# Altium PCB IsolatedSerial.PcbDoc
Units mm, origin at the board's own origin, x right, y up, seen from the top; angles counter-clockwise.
Board outline 30.48 x 40.64 mm, 2 copper layers (Top Layer, Bottom Layer), stack 1.575 mm thick; 25 components, 18 nets, 112 pads, 19 vias.
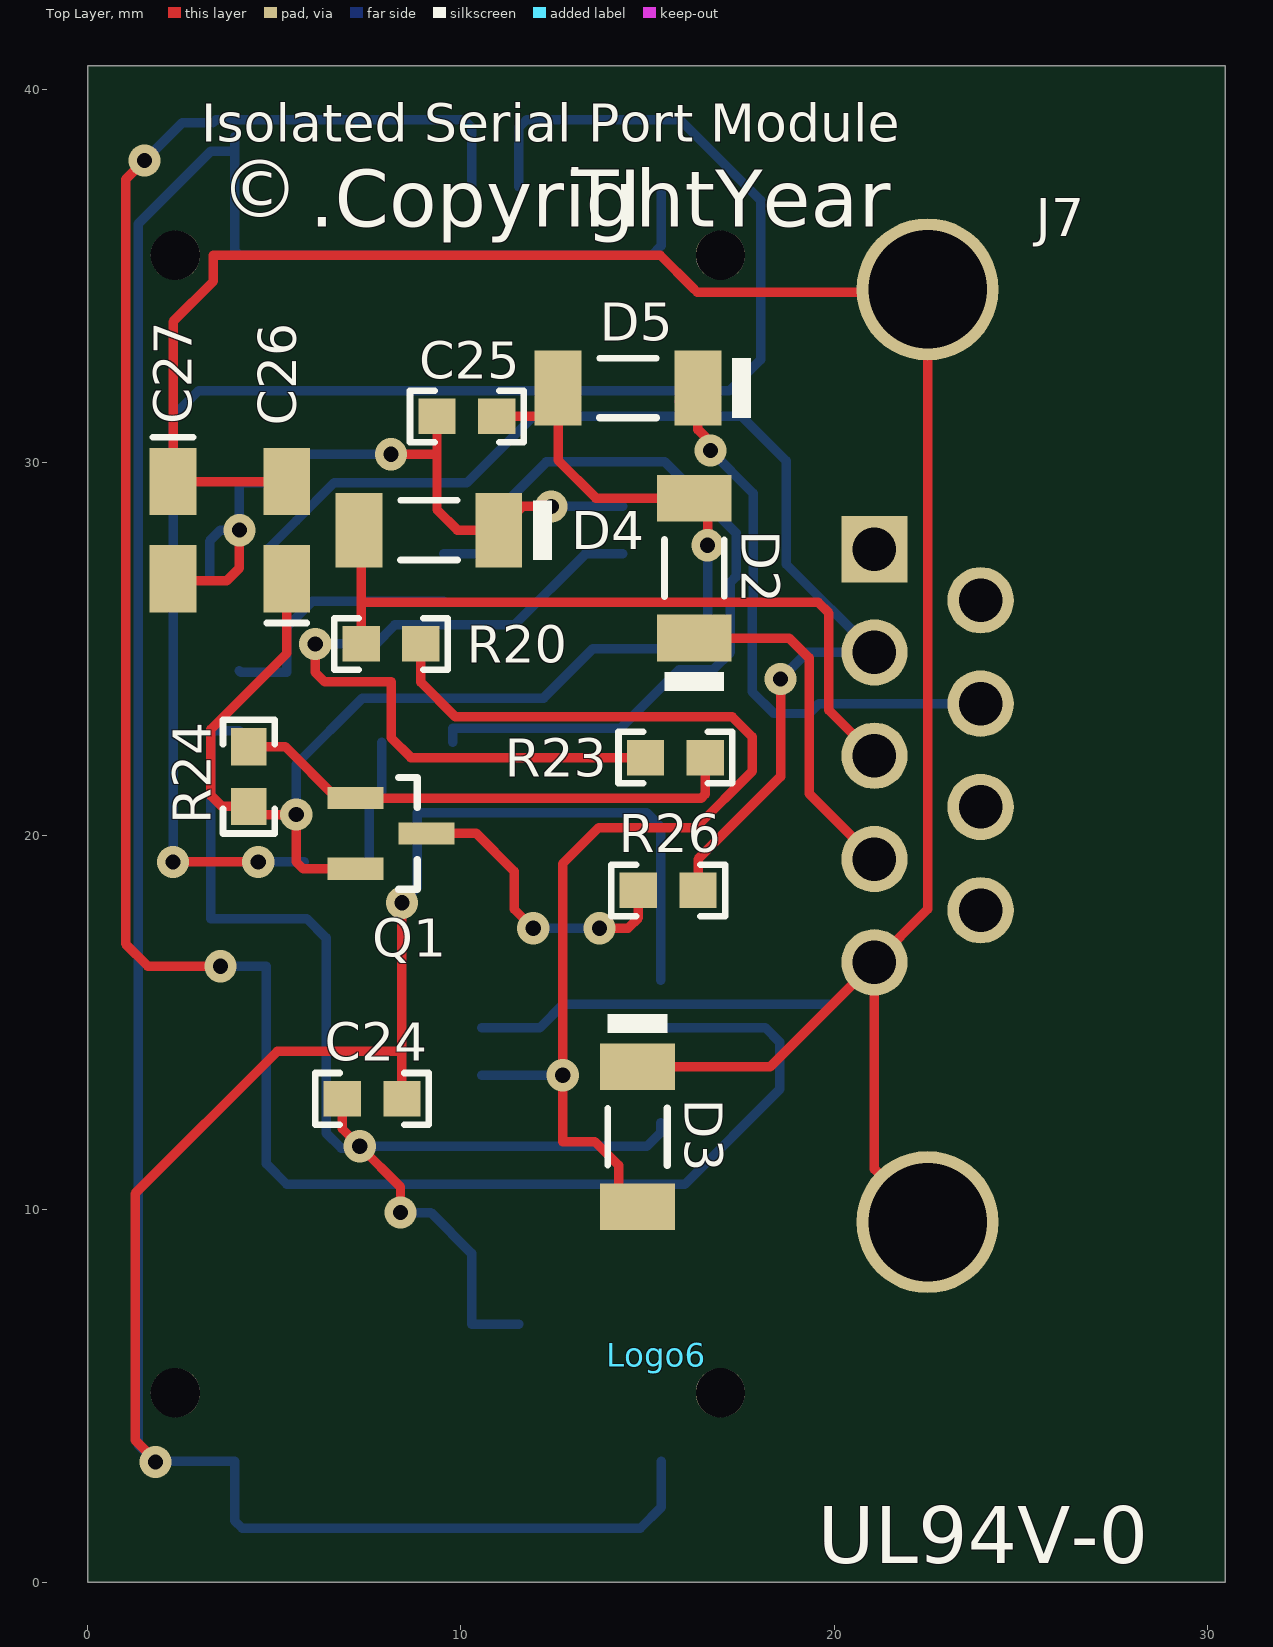
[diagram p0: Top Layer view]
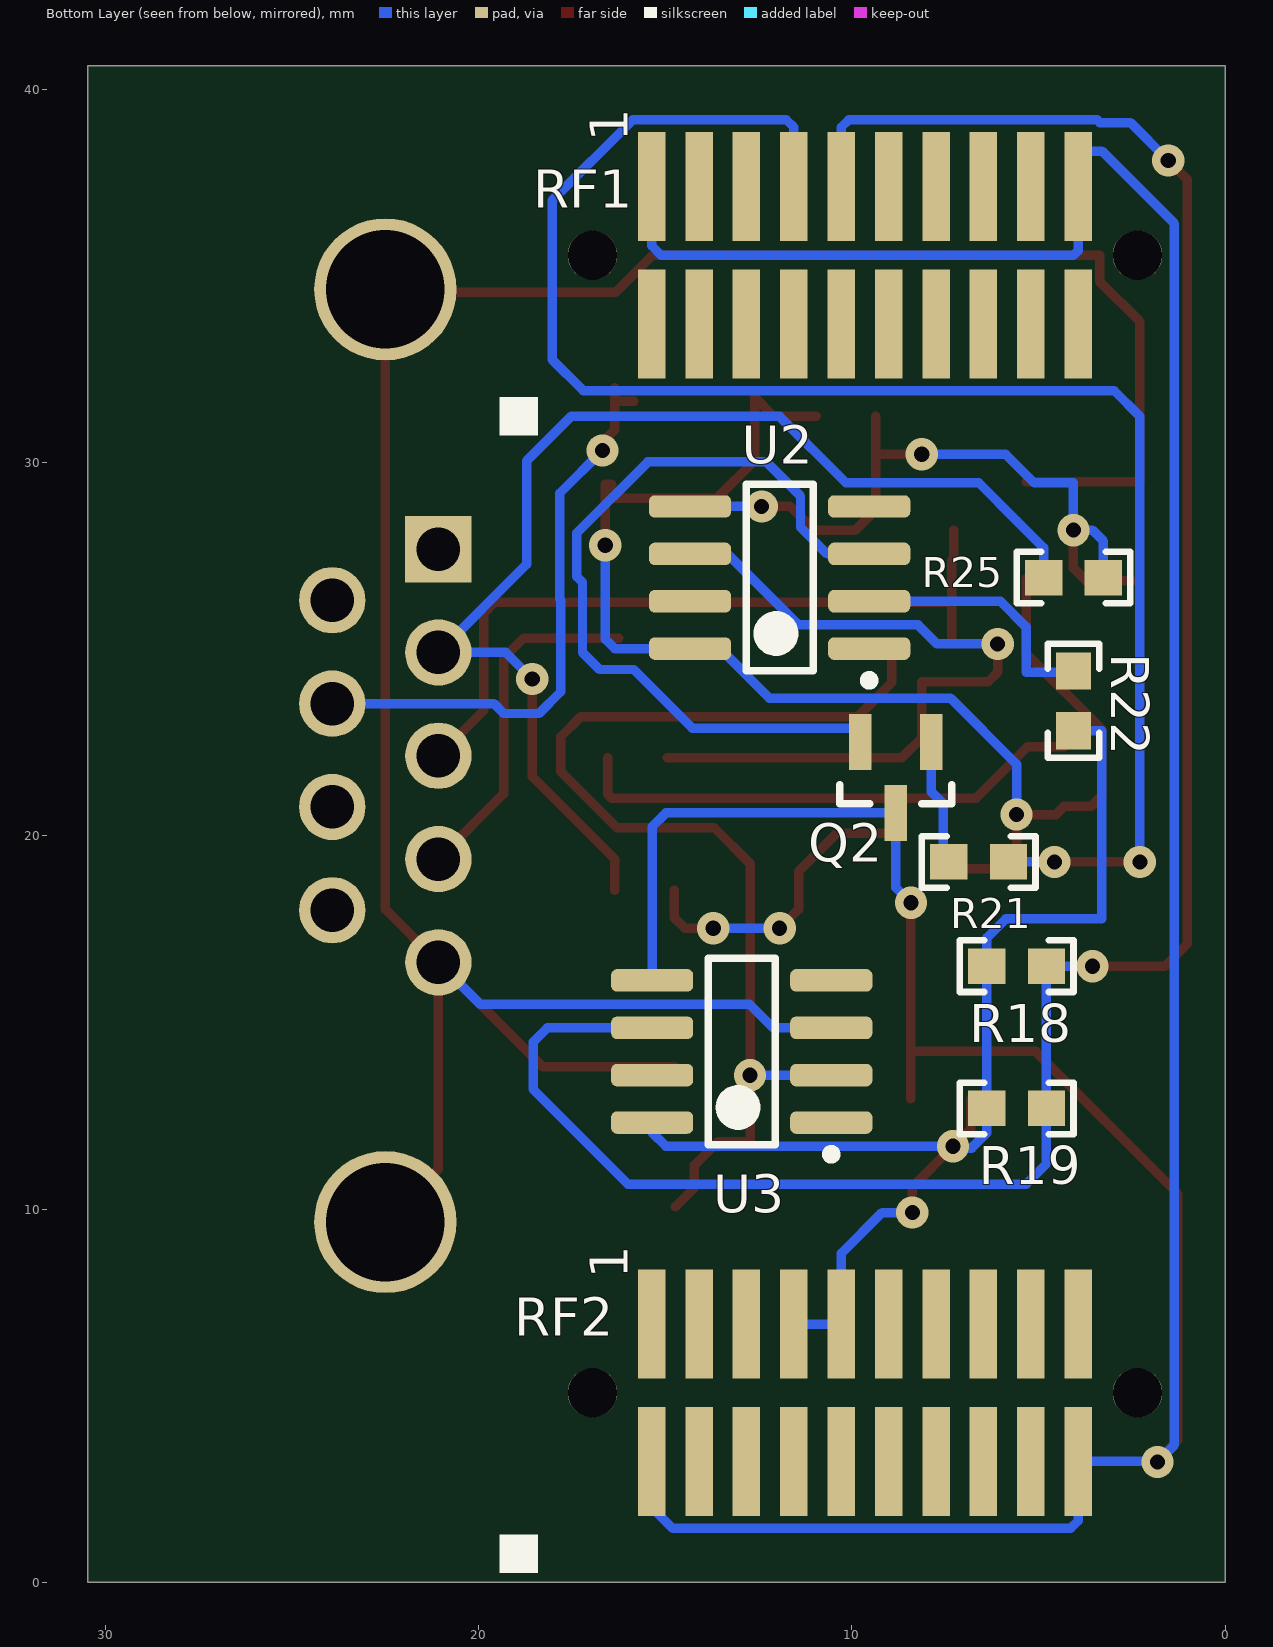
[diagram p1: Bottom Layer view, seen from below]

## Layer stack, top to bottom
Top Layer: signal copper 0.0356
Dielectric: core 1.5037, FR-4, Dk 4.8
Bottom Layer: signal copper 0.0356

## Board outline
0,0 0,40.64 30.48,40.64 30.48,0

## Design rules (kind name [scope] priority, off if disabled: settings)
AcuteAngle [All] p1: minimum=4.50000000000000E+0001 checktracksonly=FALSE
AssemblyTestPointUsage [All] p1: valid=2
Clearance Clearance_BoardEdge_MountingHoles [OnCopper and InComponentClass('Mounting Holes') vs IsKeepOut] p1: gap=1.016
Clearance Clearance_BoardEdge_Poly [OnCopper and InPoly vs IsKeepOut] p2: gap=0.635
Clearance Clearance_BoardEdge [OnCopper and Not InComponentClass('Logo') and not InComponentClass('FiducialMark') and not InRegion(1000,500,4000,800) and Not IsKeepout vs IsKeepOut] p3: gap=1.905
Clearance Clearance_Poly [InPolygon] p4: gap=0.635
Clearance [All] p5: gap=0.203
ComponentClearance ComponentClearance_Shunt [InComponentClass('Header') vs InComponentClass('Shunt')] p1: gap=0 collisioncheckmode=3 verticalgap=0 showdistances=FALSE
ComponentClearance ComponentClearance_Logo [InComponentClass('Logo')] p2: gap=1.27 collisioncheckmode=3 verticalgap=0.254 showdistances=FALSE
ComponentClearance ComponentClearance_ScrewToNut [(HasFootprint('NY PMS 440 0025 PH')) vs (HasFootprint('Keystone_1902C'))] p3: gap=0.127 collisioncheckmode=3 verticalgap=0.254 showdistances=FALSE
ComponentClearance ComponentClearance_MountingHoles [InComponentClass('Mounting Holes')] p4: gap=6.35 collisioncheckmode=3 verticalgap=2540 showdistances=FALSE
ComponentClearance ComponentClearance_SmallPassives [HasFootprint('0201*') or HasFootprint('0402*') or HasFootprint('0508') or HasFootprint('0603*') or HasFootprint('0612') or HasFootprint('0805*') or HasFootprint('0815*') or HasFootprint('0830*') or HasFootprint('1206*') or HasFootprint('1210*') or HasFootprint('1808*') or HasFootprint('1812*') or HasFootprint('1825*') or HasFootprint('2010*') or HasFootprint('2220*') or HasFootprint('2225*') or HasFootprint('2512*') or HasFootprint('2728*') or HasFootprint('3518*') vs HasFootprint('0201*') or HasFootprint('0402*') or HasFootprint('0508') or HasFootprint('0603*') or HasFootprint('0612') or HasFootprint('0805*') or HasFootprint('0815*') or HasFootprint('0830*') or HasFootprint('1206*') or HasFootprint('1210*') or HasFootprint('1808*') or HasFootprint('1812*') or HasFootprint('1825*') or HasFootprint('2010*') or HasFootprint('2220*') or HasFootprint('2225*') or HasFootprint('2512*') or HasFootprint('2728*') or HasFootprint('3518*')] p5: gap=0.508 collisioncheckmode=3 verticalgap=0.254 showdistances=FALSE
ComponentClearance ComponentClearance_THtoSMT [IsThruComponent vs IsSMTComponent] p6: gap=1.27 collisioncheckmode=3 verticalgap=0.762 showdistances=FALSE
ComponentClearance ComponentClearance_THtoTH [IsThruComponent vs IsThruComponent] p7: gap=3 collisioncheckmode=3 verticalgap=0.762 showdistances=FALSE
ComponentClearance [All] p8: gap=1 collisioncheckmode=3 verticalgap=0.254 showdistances=FALSE
DiffPairsRouting [All] p1: maxlimit=2.54 minlimit=0.254 mostfreqgap=0.254 maxuncoupledlength=25.4
FabricationTestPointUsage TestPointUsage [All] p1: valid=2 allowmultiple=FALSE
FabricationTestpoint Testpoint [All] p1: side=3 testpointundercomponent=TRUE minsize=1.016 maxsize=2.54 preferedsize=1.524 minholesize=0 maxholesize=1.016 preferedholesize=0.813 testpointgrid=0.025 allowsidetop=TRUE allowsidebottom=TRUE usegrid=TRUE gridtolerance=0
FanoutControl Fanout_LCC [IsLCC] p1: bgadir=Out bgaviamode=Centered fanoutstyle=Auto fanoutdirection=Alternating viagrid=0.025 // Fanout_LCC (Default Rule)
FanoutControl Fanout_BGA [IsBGA] p2: bgadir=Out bgaviamode=Centered fanoutstyle=Auto fanoutdirection=Alternating viagrid=0.025 // Fanout_BGA (Default Rule)
FanoutControl Fanout_Default [All] p4: bgadir=Out bgaviamode=Centered fanoutstyle=Auto fanoutdirection=Alternating viagrid=0.025 // Fanout_Default (Default Rule)
FanoutControl Fanout_Small [(CompPinCount < 5)] p5: bgadir=Out bgaviamode=Centered fanoutstyle=Auto fanoutdirection=OutThenIn viagrid=0.025 // Fanout_Small (Default Rule)
HoleSize [All] p1: absolutevalues=TRUE maxlimit=6.375 minlimit=0.203 maxpercent=80.000 minpercent=20.000
MinimumAnnularRing MinimumAnnularRing_ThermalPadVias [IsVia and InAnyComponent] p1: minimumring=0.15
MinimumAnnularRing [All] p2: minimumring=0.229
MinimumSolderMaskSliver MinimumSolderMaskSliver_Logo [InComponentClass('Logo') vs InComponentClass('Logo')] p1: minsoldermaskwidth=0.018
MinimumSolderMaskSliver [All] p2: minsoldermaskwidth=0.1
PlaneConnect [All] p1: planeconnectstyle=Relief reliefexpansion=0.254 reliefentries=4 reliefconductorwidth=0.254 reliefairgap=0.254
PolygonConnect [All] p1: connectstyle=Relief reliefconductorwidth=0.254 reliefentries=4 polygonreliefangle="90 Angle" airgapwidth=0.254
RoutingVias ThermalPadVias [IsVia and InAnyComponent] p1: holewidth=0.127 width=0.254 viastyle="Through Hole" minholewidth=0.127 minwidth=0.254 maxholewidth=0.33 maxwidth=0.6
RoutingVias [All] p2: holewidth=0.406 width=0.864 viastyle="Through Hole" minholewidth=0.2 minwidth=0.66 maxholewidth=1.016 maxwidth=1.651
SMDToCorner [All] p1: distance=30000
SilkToSilkClearance [All] p1: silktosilkclearance=0.127
SilkscreenOverComponentPads [All] p1: minsilkscreentomaskgap=0.127
SolderMaskExpansion [All] p1: expansion=0.05
Width [All] p1: maxlimit=2.54 minlimit=0.127 preferedwidth=0.254 checkconnectedcopper=TRUE
14 further rules are at their usual default settings.

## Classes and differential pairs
component class Logo: Logo6

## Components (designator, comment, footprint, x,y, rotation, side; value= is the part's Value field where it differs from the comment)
C24 "C1608X7R1H104K" 0603 7.62,12.954 r0 top
C25 "C1608X7R1H104K" 0603 10.16,31.242 r0 top
C26 "T495A106K010ATE1K8" 3216-18 5.334,28.194 r90 top
C27 "T495A106K010ATE1K8" 3216-18 2.286,28.194 r270 top
D2 "LL103A" SOD-80 16.256,27.178 r90 top
D3 "LL103A" SOD-80 14.732,11.938 r270 top
D4 "LL103A" SOD-80 9.144,28.194 r180 top
D5 "LL103A" SOD-80 14.478,32.004 r180 top
J7 "D Connector 9" DSUB9-F 21.082,27.686 r90 top
Logo6 "Texas Instruments" TI_Stacked_SolderMask_Medium 15.24,6.096 r0 top
Q1 "BC857C-7-F" SOT-23 8.128,20.066 r0 top
Q2 "BC857C-7-F" SOT-23 8.828,21.566 r270 bottom
R18 "Used in BOM report" 0603 5.588,16.51 r180 bottom
R19 "Used in BOM report" 0603 5.588,12.7 r0 bottom
R20 "Used in BOM report" 0603 8.128,25.146 r180 top
R21 "Used in BOM report" 0603 6.604,19.304 r0 bottom
R22 "Used in BOM report" 0603 4.064,23.622 r90 bottom
R23 "Used in BOM report" 0603 15.748,22.098 r0 top
R24 "Used in BOM report" 0603 4.318,21.59 r270 top
R25 "Used in BOM report" 0603 4.064,26.924 r0 bottom
R26 "Used in BOM report" 0603 15.556,18.542 r180 top
RF1 "HEADER_SFM-110-02-SM-D-A-K-TR" HEADER_TFM-110-02-SM 9.652,35.56 r180 bottom
RF2 "HEADER_SFM-110-02-SM-D-A-K-TR" HEADER_TFM-110-02-SM 9.652,5.08 r180 bottom
U2 "PS8802-1" SO-8 11.938,26.924 r0 bottom
U3 "PS8802-1" SO-8 12.954,14.224 r0 bottom

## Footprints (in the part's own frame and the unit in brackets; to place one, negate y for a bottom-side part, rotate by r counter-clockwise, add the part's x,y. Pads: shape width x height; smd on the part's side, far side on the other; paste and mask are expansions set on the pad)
0603 [mm] "0603 from SM-752 data"
  rect 1x0.95 smd: 1(-0.8,0) 2(0.8,0)
  silkscreen extent -1.52,-0.69 1.52,0.69, body extent -0.87,-0.47 0.87,0.47, height 0.85
3216-18 [mm] "Medium density IPC, based on Kemet T495 dimensions"
  rect 1.8x1.25 smd: 1(-1.3,0) 2(1.3,0)
  silkscreen extent -2.49,-0.54 -2.49,0.54, body extent -1.7,-0.9 1.7,0.9, height 1.8
DSUB9-F [mil]
  rect 70x70 hole 46: 1(0,0)
  round 70 hole 46: 2(-109,0) 3(-218,0) 4(-327,0) 5(-436,0) 6(-54,-112) 7(-163,-112) 8(-272,-112) 9(-381,-112)
  round 150 hole 125: 10(-710,-56) 11(274,-56)
HEADER_TFM-110-02-SM [mil]
  rect 29x115 smd: 1(-225,72.5) 2(-225,-72.5) 3(-175,72.5) 4(-175,-72.5) 5(-125,72.5) 6(-125,-72.5) 7(-75,72.5) 8(-75,-72.5) 9(-25,72.5) 10(-25,-72.5) 11(25,72.5) 12(25,-72.5) 13(75,72.5) 14(75,-72.5) 15(125,72.5) 16(125,-72.5) 17(175,72.5) 18(175,-72.5) 19(225,72.5) 20(225,-72.5)
  round 52 hole 52 unplated: 21(287.5,0) 22(-287.5,0)
  silkscreen extent -385,-190 -345,-150
SO-8 [mm] "SOIC, 8-Leads, Body 5.0x4.0mm (max), Pitch 1.27mm, IPC Medium Density"
  rrect50% 2.2x0.6 smd: 1(-2.4,1.905) 2(-2.4,0.635) 3(-2.4,-0.635) 4(-2.4,-1.905) 5(2.4,-1.905) 6(2.4,-0.635) 7(2.4,0.635) 8(2.4,1.905)
  silkscreen extent -2.52,-2.5 0.9,2.88, body extent -3,-2.45 3,2.45, height 1.59
SOD-80 [mm] "VISHAY"
  rect 1.25x2 smd: 1(-1.875,0) 2(1.875,0)
  silkscreen extent -3.29,-0.8 0.76,0.8, body extent -1.85,-0.81 1.85,0.81, height 1.62
SOT-23 [mm] "SOT23, 3-Leads, Body 2.9x1.3mm, Pitch 0.95mm, Lead Span 2.5mm, IPC Medium Density"
  rect 1.5x0.6 smd: 1(-0.95,0.95) 2(-0.95,-0.95) 3(0.95,0)
  silkscreen extent 0.2,-1.5 0.7,1.5, body extent -1.16,-1.45 1.21,1.45, height 1
TI_Stacked_SolderMask_Medium [mm]
  rect 0x0 smd paste-4.978 mask-4.978: 0(0,0)

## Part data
C24 C25: "CAP, CERM, 0.1uF, 50V, +/-10%, X7R, 0603"
C26 C27: "CAP, TA, 10uF, 10V, +/-10%, 1.8 ohm, SMD"
J7: "Receptacle Assembly, 9 Position, Right Angle"
Logo6: library part TI_Logo, "Texas Instrument Corporate Signature"
Q1 Q2: library part "BC857C-7-F, Diodes Inc.", "Transistor, PNP, 45V, 0.1A, SOT-23"
R18 R19 R20 R21 R22 R23 R24 R25 R26: library part Resistor, "RES, xxx ohm, x%, xW, [PackageReference]"
RF1 RF2: library part HEADER_TFM-110-02-SM-D-A-K-TR, "Header, SMT 10X2 pin, Shrouded"

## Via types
v1: diameter 0.864, hole 0.406, Top Layer to Bottom Layer, 19 vias

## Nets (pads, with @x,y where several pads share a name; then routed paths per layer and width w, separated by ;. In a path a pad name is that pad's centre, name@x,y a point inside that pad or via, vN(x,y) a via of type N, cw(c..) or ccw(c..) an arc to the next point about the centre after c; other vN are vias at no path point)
DGND: C24.2 Q2.3 RF1.1 RF1.19 RF2.2 RF2.20 U3.5 | length 104.3
  Top Layer w0.254: v1@1.778,3.302 1.27,3.81 1.27,10.414 5.08,14.224 8.42,14.224 ; C24.2 v1(8.42,18.21)
  Bottom Layer w0.254: RF1.19@3.937,38.735 RF1.19@3.937,38.354 ; v1(8.42,18.21) 8.828,18.618 8.828,19.874 Q2.3 14.986,20.616 15.354,20.248 U3.5 ; 11.176,35.56 4.064,35.56 3.937,35.687 RF1.19 RF1.19@3.937,38.354 ; 11.213,35.56 15.113,35.56 15.367,35.814 RF1.1 ; RF2.2 15.367,2.007 14.808,1.448 4.14,1.448 3.937,1.651 RF2.20 1.83,3.238 v1(1.816,3.224) 1.359,3.681 1.359,36.411 3.302,38.354 RF1.19@3.937,38.354
MCU_RXD: R18.2 R19.1 RF1.9 U3.6 | length 61.1
  Top Layer w0.254: v1(1.524,38.1) 1.016,37.592 1.016,17.107 1.613,16.51 v1(3.556,16.51)
  Bottom Layer w0.254: v1(1.524,38.1) 2.54,39.116 3.356,39.116 3.432,39.192 10.084,39.192 10.287,38.989 RF1.9 ; v1(3.556,16.51) R18.2 R19.1 4.788,11.214 5.334,10.668 16.002,10.668 18.542,13.208 18.542,14.478 18.161,14.859 U3.6
MCU_TXD: R21.1 RF1.7 | length 45.1
  Top Layer w0.254: v1(2.286,19.304) v1(4.572,19.304)
  Bottom Layer w0.254: v1(2.286,19.304) 2.286,31.242 2.972,31.928 17.196,31.928 18.034,32.766 18.034,37.03 15.872,39.192 11.76,39.192 11.557,38.989 RF1.7 ; v1(4.572,19.304) R21.1
NetC25_1: C25.1 C27.2 D4.1 R25.1 U2.5 | length 19.5
  Top Layer w0.254: C27.2@2.49,26.844 3.73,26.844 4.064,27.178 v1(4.064,28.194) ; v1(8.128,30.226) 9.36,30.226 ; C25.1 9.36,28.74 9.906,28.194 D4.1 11.654,28.829 v1(12.421,28.829)
  Bottom Layer w0.254: R25.1 3.264,27.902 3.556,28.194 v1(4.064,28.194) 4.064,29.464 5.118,29.464 5.88,30.226 v1(8.128,30.226) ; v1(12.421,28.829) U2.5
NetC25_2: C25.2 C26.1 D2.2 D5.2 Q1.2 R24.2 U2.8 | length 38.4
  Top Layer w0.254: C26.1 5.334,24.892 3.302,22.86 3.302,21.082 3.594,20.79 R24.2 4.534,20.574 v1(5.588,20.574) 5.588,19.304 5.776,19.116 Q1.2 ; C25.2 12.095,31.242 12.603,31.75 12.603,30.069 13.619,29.053 D2.2 D2.2@16.612,29.053 ; v1(16.612,27.788) 16.612,29.428 16.449,29.428 16.434,29.413 D2.2@16.612,29.235
  Bottom Layer w0.254: v1(5.588,20.574) 5.588,21.92 7.363,23.696 12.215,23.696 13.538,25.019 U2.8 16.358,25.019 16.612,25.273 v1(16.612,27.788)
NetC26_2: C26.2 C27.1 D3.1 J7.5 J7.10 J7.11 U3.3 | length 74.1
  Top Layer w0.254: C26.2 2.336,29.494 2.286,29.445 2.286,33.782 3.365,34.861 3.365,35.56 15.342,35.56 16.205,34.696 16.332,34.569 22.428,34.569 J7.11 22.504,18.034 J7.5 ; D3.1 18.283,13.813 J7.5 ; J7.10 21.082,11.074 J7.5
  Bottom Layer w0.254: U3.3 12.116,14.859 12.751,15.494 19.964,15.494 J7.5
NetD2_1: D2.1 J7.4 | length 9.4
  Top Layer w0.254: D2.1 18.796,25.303 19.329,24.77 19.329,21.133 J7.4
NetD3_2: D3.2 R20.1 U3.2 | length 30.2
  Top Layer w0.254: R20.1 8.928,24.117 9.855,23.19 17.272,23.19 17.805,22.657 17.805,21.731 16.293,20.218 13.691,20.218 12.73,19.258 12.73,11.811 13.589,11.811 14.224,11.176 14.224,10.571 D3.2
  Bottom Layer w0.254: U3.2 v1(12.73,13.589)
NetD4_2: D4.2 J7.3 R20.2 | length 20.5
  Top Layer w0.254: D4.2 7.269,27.453 7.328,27.394 7.328,26.619 7.328,25.768 ; R20.2 7.328,26.251 7.341,26.264 19.573,26.264 19.863,25.974 19.863,23.368 J7.3
NetD5_1: D5.1 J7.7 | length 15.8
  Top Layer w0.254: D5.1@15.845,31.653 15.845,31.648 D5.1@16.353,31.648 ; D5.1@16.353,31.75 D5.1@16.353,31.648 ; D5.1 D5.1@16.353,31.648 ; v1(16.688,30.328) 16.688,30.556 16.353,30.891 D5.1@16.353,31.648
  Bottom Layer w0.254: v1(16.688,30.328) 17.831,29.185 17.831,26.34 17.805,26.314 17.805,23.865 18.39,23.281 19.329,23.281 19.594,23.546 J7.7
NetJ7_2: J7.2 R25.2 R26.1 | length 32.1
  Top Layer w0.254: R26.1 16.356,19.38 18.567,21.592 v1(18.567,24.206)
  Bottom Layer w0.254: R25.2 4.864,27.724 5.588,28.448 6.604,29.464 10.16,29.464 11.938,31.242 17.526,31.242 18.72,30.048 18.72,27.28 J7.2 19.279,24.917 v1(18.567,24.206)
NetQ1_1: Q1.1 R23.2 R24.1 | length 13.8
  Top Layer w0.254: R24.1 5.296,22.39 6.67,21.016 Q1.1 16.444,21.016 16.548,21.12 R23.2
NetQ1_3: Q1.3 R26.2 | length 8.2
  Top Layer w0.254: Q1.3 10.414,20.066 11.43,19.05 11.43,18.034 v1(11.938,17.526) ; v1(13.716,17.526) 14.478,17.526 14.756,17.804 R26.2
  Bottom Layer w0.254: v1(11.938,17.526) v1(13.716,17.526)
NetQ2_1: Q2.1 R21.2 | length 3.3
  Bottom Layer w0.254: R21.2@7.549,19.304 7.549,20.859 7.878,21.189 Q2.1
NetQ2_2: Q2.2 U2.3 | length 22.1
  Bottom Layer w0.254: U2.3 10.668,27.559 11.379,28.27 11.379,29.108 12.294,30.023 15.469,30.023 17.374,28.118 17.374,26.949 17.221,26.797 17.221,24.917 16.764,24.46 15.85,24.46 14.275,22.885 9.778,22.885 Q2.2
NetR22_2: R22.2 U2.2 | length 7
  Bottom Layer w0.254: R22.2 4.102,24.384 5.334,24.384 5.334,25.603 6.02,26.289 U2.2
NetR23_1: R23.1 U2.6 | length 20.7
  Top Layer w0.254: v1(6.096,25.146) 6.096,24.384 6.35,24.13 8.128,24.13 8.128,22.631 8.661,22.098 R23.1
  Bottom Layer w0.254: v1(6.096,25.146) 7.722,25.146 8.23,25.654 11.43,25.654 13.335,27.559 U2.6
VCC: C24.1 R18.1 R19.2 R22.1 RF2.7 RF2.9 U3.8 | length 33.6
  Top Layer w0.254: C24.1 6.82,12.154 v1(7.29,11.684) 8.382,10.592 v1(8.382,9.906)
  Bottom Layer w0.254: R22.1 3.302,22.822 3.302,17.78 5.874,17.78 6.388,17.266 R18.1 R19.2 6.388,12.586 6.388,12.04 6.794,11.634 ; v1@7.138,11.836 6.935,11.634 6.794,11.634 ; v1@7.621,11.634 6.794,11.634 ; v1@7.621,11.684 14.402,11.684 14.986,11.684 15.354,12.052 U3.8 ; v1(8.382,9.906) 9.195,9.906 10.287,8.814 RF2.9 10.287,6.909 11.557,6.909 RF2.7
pads on no net: J7.1 J7.6 J7.8 J7.9 Logo6.0 RF1.2 RF1.3 RF1.4 RF1.5 RF1.6 RF1.8 RF1.10 RF1.11 RF1.12 RF1.13 RF1.14 RF1.15 RF1.16 RF1.17 RF1.18 RF1.20 RF1.21 RF1.22 RF2.1 RF2.3 RF2.4 RF2.5 RF2.6 RF2.8 RF2.10 RF2.11 RF2.12 RF2.13 RF2.14 RF2.15 RF2.16 RF2.17 RF2.18 RF2.19 RF2.21 RF2.22 U2.1 U2.4 U2.7 U3.1 U3.4 U3.7

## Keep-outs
Keep-Out Layer:
  lines w0.254: 125.73,-0.127 ccw(c125.73,0) 125.857,0 ; 125.73,-0.127 ccw(c125.73,0) 125.857,0 ; 125.73,-0.127 ccw(c125.73,0) 125.857,0 ; 125.73,-0.127 ccw(c125.73,0) 125.857,0 ; 125.73,-0.127 ccw(c125.73,0) 125.857,0 ; 125.73,-0.127 ccw(c125.73,0) 125.857,0
  text ".Layer_Name" at 14.656,-21.806 h1.52

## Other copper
Top Layer:
  text ".Layer_Name" at 14.656,-21.806 h1.52
Bottom Layer:
  text ".Layer_Name" at 14.656,-21.806 h1.52

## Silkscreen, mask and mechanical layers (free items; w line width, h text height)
Top Overlay:
  text "Isolated Serial Port Module" at 3.048,38.608 h1.02
  text ".CopyrightYear" at 5.944,36.322 h1.52
  text "TI" at 12.954,36.322 h1.52
  text "©" at 3.556,36.068 h2.67
  text "UL94V-0" at 19.558,0.508 h1.52
  text ".Layer_Name" at 14.656,-21.806 h1.52
Bottom Overlay:
  text "1" at 16.002,38.608 h1.02 r270
  text "1" at 16.002,8.128 h1.02 r270
  text ".Layer_Name" at 14.656,-21.806 h1.52
Top Paste:
  text ".Layer_Name" at 14.656,-21.806 h1.52
Bottom Paste:
  text ".Layer_Name" at 14.656,-21.806 h1.52
Top Solder:
  text ".Layer_Name" at 14.656,-21.806 h1.52
  text ".Layer_Name" at 14.656,-21.806 h1.52
Bottom Solder:
  text ".Layer_Name" at 14.656,-21.806 h1.52
Drill Guide:
  text ".Layer_Name" at 14.656,-21.806 h1.52
M1 Board Outline:
  the board outline again, w0.254
  text ".Layer_Name" at 14.656,-21.806 h1.52
M2 Board Dimensions:
  rectangle: 3.162,-10.427 12.687,-7.252
  rectangle: -0.013,-7.252 3.162,-4.077
  lines w0.178: -0.013,-7.252 25.387,-7.252 ; 3.162,-10.427 3.162,-4.077 ; 6.337,-10.427 6.337,-4.077 ; 12.687,-10.427 12.687,-4.077 ; 19.037,-10.427 19.037,-4.077 ; -0.013,-10.427 -0.013,-4.077 25.387,-4.077 25.387,-10.427 -0.013,-10.427
  lines w0.254: -4.826,1.524 -4.318,0 ; -4.826,39.116 -4.318,40.64 ; -4.572,0 -4.064,0 ; -4.572,40.64 -4.064,40.64 ; -4.318,13.058 -4.318,0 ; -4.318,27.582 -4.318,40.64 ; -3.81,1.524 -4.318,0 ; -3.81,39.116 -4.318,40.64 ; -0.013,-12.078 -0.013,-11.57 ; 1.511,-12.332 -0.013,-11.824 ; 1.511,-11.316 -0.013,-11.824 ; 6.187,-11.824 -0.013,-11.824 ; 19.188,-11.824 25.387,-11.824 ; 23.863,-12.332 25.387,-11.824 ; 23.863,-11.316 25.387,-11.824 ; 25.387,-12.078 25.387,-11.57
  text "40.64 (mm)" at -3.404,13.312 h1.52 r90
  text "25.4 (mm)" at 6.441,-12.738 h1.52
  text ".Layer_Name" at 14.656,-21.806 h1.52
M3 3D STEP Top:
  text ".Layer_Name" at 14.656,-21.806 h1.52
M4 3D STEP Bottom:
  text ".Layer_Name" at 14.656,-21.806 h1.52
M5 Assembly Top:
  lines w0.254: -7.417,-23.626 160.223,-23.626 ; -7.417,-18.462 160.274,-18.462 ; -7.417,-13.297 -7.417,-28.791 94.31,-28.791 160.274,-28.791 160.274,-13.297 -7.404,-13.297 -7.404,-28.791 32.614,-28.791 ; 55.194,-28.791 55.194,-13.297 ; 87.376,-18.462 87.376,-13.297 ; 108.712,-18.462 108.712,-13.297 ; 124.511,-28.956 124.511,-23.804
  text "COMPONENTS MARKED 'DNP' SHOULD NOT BE POPULATED." at 29.299,-8.09 h1.52
  text "ASSEMBLY VARIANT:" at 29.286,-11.024 h1.52
  text ".VariantName" at 55.601,-11.024 h1.52
  text "PCB VIEWED FROM TOP SIDE" at -5.804,-16.654 h1.52
  text "BOARD #:" at 57.099,-16.654 h1.52
  text ".PRJ_Number" at 70.955,-16.654 h1.52
  text "REV:" at 92.405,-16.654 h1.52
  text ".PCB_Rev" at 99.809,-16.654 h1.52
  text "SVN REV:" at 113.69,-16.654 h1.52
  text ".VersionControl_RevNumber" at 126.543,-16.654 h1.52
  text "IGNORE ->" at -5.804,-21.806 h1.52
  text "PLOT NAME =" at -5.804,-27.034 h1.52
  text ".plot_File_Name" at 14.656,-27.034 h1.52
  text "GENERATED    :" at 57.15,-27.034 h1.52
  text ".Print_Date" at 79.235,-27.034 h1.52
  text ".Print_Time" at 97.752,-27.034 h1.52
  text "TEXAS INSTRUMENTS" at 129.87,-27.034 h1.52
M6 Assembly Bottom:
  lines w0.254: -7.429,-18.474 160.261,-18.474 ; -7.379,-23.639 160.261,-23.639 ; 28.334,-28.969 28.334,-23.817 ; 44.133,-18.474 44.133,-13.31 ; 65.468,-18.474 65.468,-13.31 ; 97.65,-28.804 97.65,-13.31 ; 120.231,-28.804 160.249,-28.804 160.249,-13.31 -7.429,-13.31 -7.429,-28.804 58.534,-28.804 160.261,-28.804 160.261,-13.31
  text "COMPONENTS MARKED 'DNP' SHOULD NOT BE POPULATED." at 154.991,-8.077 h1.52
  text ".VariantName" at 128.473,-11.024 h1.52
  text "ASSEMBLY VARIANT:" at 154.864,-11.024 h1.52
  text ".VersionControl_RevNumber" at 26.302,-16.667 h1.52
  text "SVN REV:" at 39.154,-16.667 h1.52
  text ".PCB_Rev" at 53.035,-16.667 h1.52
  text "REV:" at 60.439,-16.667 h1.52
  text ".PRJ_Number" at 81.89,-16.667 h1.52
  text "BOARD #:" at 95.745,-16.667 h1.52
  text "PCB VIEWED FROM BOTTOM SIDE" at 158.648,-16.667 h1.52
  text "IGNORE ->" at 64.715,-21.806 h1.52
  text "TEXAS INSTRUMENTS" at 22.974,-27.047 h1.52
  text ".Print_Time" at 55.093,-27.047 h1.52
  text ".Print_Date" at 73.609,-27.047 h1.52
  text "GENERATED    :" at 95.694,-27.047 h1.52
  text ".plot_File_Name" at 138.189,-27.047 h1.52
  text "PLOT NAME =" at 158.648,-27.047 h1.52
M9 Title Sheet:
  drawing of 57 lines, arcs and shapes, not listed
  text "1" at 18.792,204.127 h1.78
  text "2" at 82.182,204.127 h1.78
  text "3" at 145.411,204.127 h1.78
  text "4" at 209.08,204.127 h1.78
  text "5" at 272.555,204.127 h1.78
  text "6" at 336.182,204.127 h1.78
  text "A" at -10.579,175.095 h1.78
  text "A" at 365.341,175.095 h1.78
  text "B" at -10.579,114.643 h1.78
  text "B" at 365.341,114.643 h1.78
  text "C" at -10.579,54.318 h1.78
  text "C" at 365.341,54.318 h1.78
  text "PROJECT TITLE:" at 288.125,7.048 h1.14
  text ".PRJ_Title" at 289.395,3.662 h1.78
  text "DESIGNED FOR:" at 288.125,-0.597 h1.14
  text ".PRJ_Customer" at 289.395,-4.153 h1.78
  text "D" at -10.579,-5.88 h1.78
  text "D" at 365.341,-5.88 h1.78
  text "FILE NAME:" at 288.125,-8.217 h1.14
  text ".PCB_File_Name_No_Path" at 289.395,-11.265 h1.78
  text "Texas Instruments (TI) and/or its licensors do not warrant the accuracy or completeness of this specification" at 161.9,-15.376 h1.14
  text "ENGINEER:" at 288.125,-15.583 h1.14
  text "LAYOUT BY:" at 326.352,-15.583 h1.14
  text "or any information contained therein. TI and/or its licensors do not warrant that this design will meet" at 160.757,-18.237 h1.14
  text ".PRJ_Engineer" at 289.395,-19.52 h1.78
  text ".PCB_Layout" at 327.635,-19.52 h1.78
  text "the specifications, will be suitable for your application or fit for any particular purpose, or will operate in" at 160.757,-21.099 h1.14
  text ".Layer_Name" at 14.656,-21.806 h1.52
  text "ALTIUM DESIGNER VERSION:" at 326.352,-23.457 h1.14
  text "an implementation. TI and/or its licensors do not warrant that the design is production worthy. You should" at 160.757,-23.961 h1.14
  text "completely validate and test your design implementation to confirm the system functionality for your application." at 161.9,-26.822 h1.14
  text ".print_Scale" at 289.395,-26.843 h1.78
  text ".Application_BuildNumber" at 327.635,-26.843 h1.78
  text "1" at 18.792,-32.093 h1.78
  text "2" at 82.182,-32.093 h1.78
  text "3" at 145.411,-32.093 h1.78
  text "4" at 209.08,-32.093 h1.78
  text "5" at 272.555,-32.093 h1.78
  text "6" at 336.182,-32.093 h1.78
M10 Fab Notes:
  drawing of 212 lines, arcs and shapes, not listed
  text "DESIGN INFORMATION" at 314.478,172.974 h1.52
  text "(REFER ALSO ARRAY/PANEL PROFILING INFORMATION)" at 305.294,168.866 h1.52
  text "BOARD SIZE" at 287.87,168.758 h1.52
  text "3450MIL" at 299.613,165.511 h1.52
  text "X" at 312.457,165.511 h1.52
  text "4950MIL" at 318.333,165.511 h1.52
  text "Number of Layers :" at 298.106,160.503 h1.52
  text "2" at 325.914,160.249 h1.52
  text "MIN. TRACK WIDTH:" at 298.106,156.972 h1.52
  text "8" at 325.951,156.972 h1.52
  text "MIL" at 329.881,156.972 h1.52
  text "MIN. CLEARANCE:" at 298.106,153.619 h1.52
  text "8" at 325.951,153.619 h1.52
  text "MIL" at 329.881,153.619 h1.52
  text "MIN. VIA PAD SIZE:" at 298.106,150.266 h1.52
  text "24" at 325.189,150.266 h1.52
  text "MIL" at 329.881,150.266 h1.52
  text "0.05mm (2MIL)" at 315.759,146.667 h1.52
  text "MINIMUM ANNULAR RING" at 289.744,146.558 h1.52
  text "EXTERNAL" at 333.742,146.558 h1.52
  text "PER" at 294.824,143.561 h1.52
  text "IPC-D-275 CLASS 2 LEVEL C" at 300.412,143.561 h1.52
  text "MIL, HOLES" at 338.213,140.709 h1.52
  text "+/-" at 328.244,140.691 h1.52
  text "+/-" at 349.936,140.691 h1.52
  text "REGISTRATION TOLERANCES:" at 289.744,140.564 h1.52
  text "METAL" at 320.218,140.564 h1.52
  text "5" at 334.853,140.564 h1.52
  text "3" at 356.012,140.564 h1.52
  text "MIL" at 358.964,140.564 h1.52
  text "MATERIAL:" at 287.844,135.243 h1.52
  text "FR-4 High Tg" at 312.9,131.679 h1.52
  text "FR-408" at 298.538,131.461 h1.52
  text "X" at 309.003,131.461 h1.52
  text "OTHER" at 336.333,131.461 h1.52
  text "62 MIL (1.6mm) +/-10%" at 306.668,127.328 h1.52
  text "THICKNESS:" at 289.744,127.219 h1.52
  text "X" at 303.413,127.219 h1.52
  text "OTHER" at 339.305,127.219 h1.52
  text "TOLERANCE:" at 289.744,123.206 h1.52
  text "X" at 311.062,123.206 h1.52
  text "ANSI IPC-6012 TYPE 3 CLASS 2" at 315.81,123.206 h1.52
  text "OTHER +/-" at 315.81,119.244 h1.52
  text "BOW & TWIST:" at 289.744,115.256 h1.52
  text "X" at 311.062,115.256 h1.52
  text "ANSI IPC-6012 TYPE 3 CLASS 2" at 315.81,115.256 h1.52
  text "OTHER +/-" at 315.81,111.23 h1.52
  text "COPPER THICKNESS (FINISHED):" at 287.844,107.788 h1.52
  text "1.4MIL (1oz)" at 310.196,103.909 h1.52
  text "2MIL (1.4oz)" at 329.678,103.909 h1.52
  text "2.8MIL (2oz)" at 348.144,103.909 h1.52
  text "OUTER:" at 296.912,103.801 h1.52
  text "X" at 306.934,103.784 h1.52
  text "1.4MIL (1oz)" at 310.196,99.922 h1.52
  text "2.8MIL (2oz)" at 329.678,99.922 h1.52
  text "N/A" at 348.132,99.931 h1.52
  text "INNER SIGNAL:" at 289.57,99.813 h1.52
  text "X" at 306.97,99.813 h1.52
  text "DRILLING:" at 287.844,96.282 h1.52
  text "REFERENCE:" at 289.744,93.31 h1.52
  text "X" at 306.209,93.31 h1.52
  text "AS SHOWN" at 310.958,93.31 h1.52
  text "X" at 329.094,93.31 h1.52
  text "NC_DRILL FILES" at 332.574,93.31 h1.52
  text "PTH MIN COPPER THICKNESS:" at 289.744,89.297 h1.52
  text "X" at 324.039,89.297 h1.52
  text "1MIL" at 327.519,89.297 h1.52
  text "OTHER" at 340.143,89.297 h1.52
  text "BOARD FINISH:" at 287.844,85.259 h1.52
  text "SILKSCREEN:" at 291.787,82.261 h1.52
  text "X" at 315.886,82.261 h1.52
  text "TOP" at 319.086,82.261 h1.52
  text "X" at 328.84,82.261 h1.52
  text "BOTTOM" at 332.066,82.261 h1.52
  text "SILKSCREEN COLOR:" at 291.787,78.02 h1.52
  text "X" at 315.86,78.02 h1.52
  text "WHITE" at 319.086,78.02 h1.52
  text "OTHER" at 332.066,78.02 h1.52
  text "SOLDER RESIST COLOR:" at 291.787,73.702 h1.52
  text "X" at 306.208,69.658 h1.52
  text "GREEN" at 309.434,69.658 h1.52
  text "BLUE" at 324.446,69.658 h1.52
  text "OTHER" at 338.111,69.658 h1.52
  text "IMMERSION GOLD (ENIG)" at 314.794,64.87 h1.52
  text "ENEPIG" at 348.767,64.786 h1.52
  text "SURFACE FINISH:" at 287.844,64.761 h1.52
  text "X" at 310.045,64.761 h1.52
  text "IMM. TIN/SILVER OR EQUIV" at 296.215,60.773 h1.52
  text "OTHER" at 332.574,60.773 h1.52
  text "ARRAY/PANEL:" at 287.844,56.226 h1.52
  text "CUT AND TRIM PER MECH LAYER 1" at 314.794,56.118 h1.52
  text "N.C. ROUTE" at 314.794,52.264 h1.52
  text "X" at 332.04,52.264 h1.52
  text "V. SCORE" at 336.79,52.264 h1.52
  text "CERTIFICATION:" at 287.844,48.784 h1.52
  text "MATERIALS AND WORKMANSHIP FOR ALL PCBS" at 306.259,48.784 h1.52
  text "TO MEET OR EXCEED THE REQUIREMENTS OF:" at 306.259,46.295 h1.52
  text "X" at 296.773,42.828 h1.52
  text "ANSI IPC-A-600F CLASS ->" at 300.303,42.828 h1.52
  text "X" at 341.935,42.828 h1.52
  text "2" at 344.956,42.828 h1.52
  text "1" at 336.955,42.79 h1.52
  text "3" at 353.948,42.79 h1.52
  text "X" at 296.825,38.777 h1.52
  text "UL 94V-0" at 300.303,38.777 h1.52
  text "X" at 317.45,38.777 h1.52
  text "RoHS" at 320.928,38.777 h1.52
  text "OTHER" at 337.296,38.777 h1.52
  text "PER ORDER" at 347.381,38.777 h1.52
  text "ADDITIONAL REQUIREMENTS:" at 287.844,35.195 h1.52
  text "MICROSECTION:" at 289.744,32.274 h1.52
  text "YES" at 312.749,32.274 h1.52
  text "REQUIRED" at 334.631,28.308 h1.52
  text "BARE BOARD ELEC. TEST:" at 289.744,28.236 h1.52
  text "NONE" at 322.909,28.236 h1.52
  text "X" at 331.405,28.236 h1.52
  text "PER ORDER" at 349.668,28.236 h1.52
  text "MANUFACTURER'S UL:" at 289.744,24.248 h1.52
  text "RAIL" at 319.353,24.139 h1.52
  text "METAL" at 331.845,24.139 h1.52
  text "X" at 341.376,24.13 h1.52
  text "SILK" at 344.842,24.139 h1.52
  text ".Layer_Name" at 14.656,-21.806 h1.52
M11 Gerber Information:
  lines w0.254: -7.417,-23.626 160.223,-23.626 ; -7.417,-18.462 160.274,-18.462 ; -7.417,-13.297 -7.417,-28.791 94.31,-28.791 160.274,-28.791 160.274,-13.297 -7.404,-13.297 -7.404,-28.791 32.614,-28.791 ; 55.194,-28.791 55.194,-13.297 ; 87.376,-18.462 87.376,-13.297 ; 108.712,-18.462 108.712,-13.297 ; 124.511,-28.956 124.511,-23.804
  text "ALL ARTWORK VIEWED FROM TOP SIDE" at -5.804,-16.654 h1.52
  text "BOARD #:" at 57.099,-16.654 h1.52
  text ".PRJ_Number" at 70.955,-16.654 h1.52
  text "REV:" at 92.405,-16.654 h1.52
  text ".PCB_Rev" at 99.809,-16.654 h1.52
  text "SVN REV:" at 113.69,-16.654 h1.52
  text ".VersionControl_RevNumber" at 126.543,-16.654 h1.52
  text "LAYER NAME =" at -5.804,-21.806 h1.52
  text "PLOT NAME =" at -5.804,-27.034 h1.52
  text ".plot_File_Name" at 14.656,-27.034 h1.52
  text "GENERATED    :" at 57.15,-27.034 h1.52
  text ".Print_Date" at 79.235,-27.034 h1.52
  text ".Print_Time" at 97.752,-27.034 h1.52
  text "TEXAS INSTRUMENTS" at 129.87,-27.034 h1.52
M12 Stackup:
  lines w0.152: 288.544,189.484 353.314,189.484 ; 288.544,192.136 353.314,192.136 ; 287.02,177.165 ccw(c287.884,177.165) 287.884,176.301 353.974,176.301 ccw(c353.974,177.165) 354.838,177.165 354.838,195.097 ccw(c353.974,195.097) 353.974,195.961 287.884,195.961 ccw(c287.884,195.097) 287.02,195.097 287.02,177.165
  text "The Stackup Legend below this is static." at 294.78,200.012 h1.52
  text "If you change the stackup, update the Legend." at 295.034,197.726 h1.52
  text "Layer Stack Up Detail for: Ref_Design.PcbDoc" at 288.544,192.966 h1.45
  text "Layer" at 288.544,191.145 h0.61
  text "Gerber" at 311.298,191.145 h0.61
  text "Copper" at 325.611,191.145 h0.61
  text "Dielectric" at 340.92,191.145 h0.61
  text "Name" at 288.544,189.926 h0.61
  text "Document" at 311.298,189.926 h0.61
  text "Thickness" at 325.611,189.926 h0.61
  text "Material" at 340.92,189.926 h0.61
  text "Top Solder Mask" at 288.544,187.565 h0.86
  text "(.GTS)" at 311.298,187.565 h0.86
  text "Solder Resist" at 340.92,187.565 h0.86
  text "Top Layer" at 288.544,185.107 h0.86
  text "(.GTL)" at 311.298,185.107 h0.86
  text "1.4mil" at 325.611,185.107 h0.86
  text "FR-4" at 340.92,183.879 h0.86
  text "Bottom Layer" at 288.544,182.65 h0.86
  text "(.GBL)" at 311.298,182.65 h0.86
  text "1.4mil" at 325.611,182.65 h0.86
  text "Bottom Solder Mask" at 288.544,180.192 h0.86
  text "(.GBS)" at 311.298,180.192 h0.86
  text "Solder Resist" at 340.92,180.192 h0.86
  text ".Layer_Name" at 14.656,-21.806 h1.52
M13 Component Bodies Top:
  text ".Layer_Name" at 14.656,-21.806 h1.52
M14 Component Bodies Bottom:
  text ".Layer_Name" at 14.656,-21.806 h1.52
M15 Courtyards Top:
  text ".Layer_Name" at 14.656,-21.806 h1.52
M16 Courtyards Bottom:
  text ".Layer_Name" at 14.656,-21.806 h1.52
Drill Drawing:
  text ".Layer_Name" at 14.656,-21.806 h1.52

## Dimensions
30.48,-1.016 to 0,-1.016 on M2 Board Dimensions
